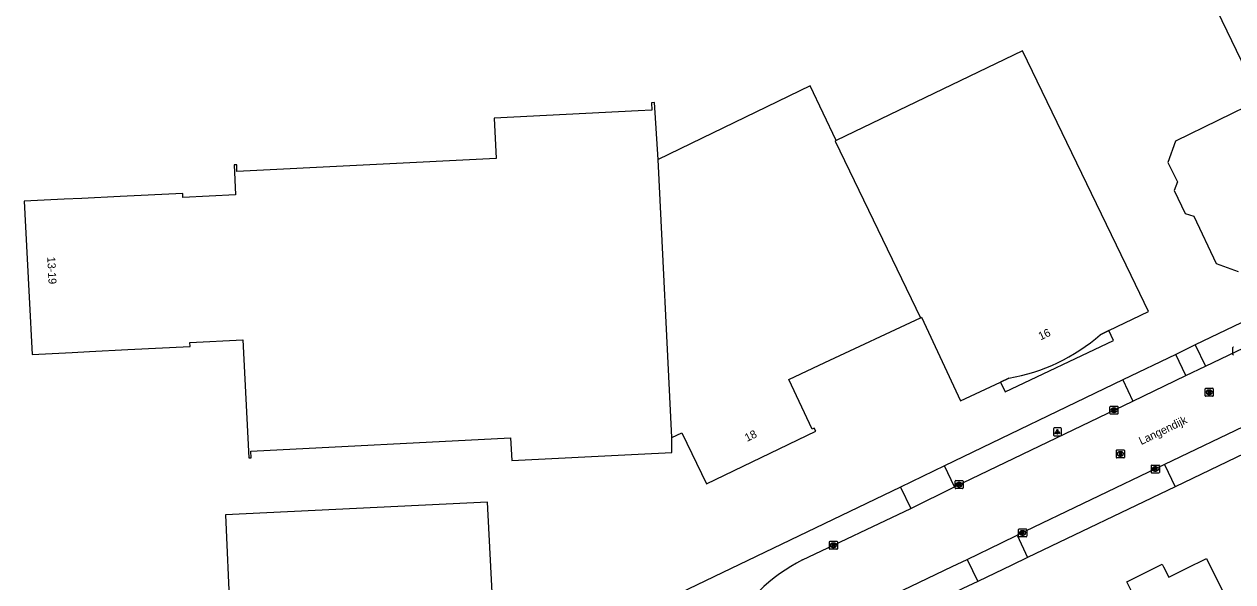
# Model space of a CAD drawing. Extents: x 157692 to 159670, y 381454 to 383289.
# Drawn here: x 157923.3 to 158074.3, y 381642.5 to 381712.2 of the extents above; entities that cross this region are included whole.
import ezdxf

# ---------------------------------------------------------------- set-up
doc = ezdxf.new("R2010")
doc.units = 0
for name, color, linetype in [('IMGEO_Kolk', 7, 'Continuous'), ('IMGEO_Lichtpunt', 7, 'Continuous'), ('IMGEO_Openbare_ruimte_label', 7, 'Continuous'), ('IMGEO_Pand', 7, 'Continuous'), ('IMGEO_Pand_nummerreeks', 7, 'Continuous'), ('IMGEO_Pand_overbouw', 7, 'Continuous'), ('IMGEO_Rijbaan_lokaal_gesloten', 7, 'Continuous'), ('IMGEO_Rioolput', 7, 'Continuous'), ('IMGEO_Voetpad_open', 7, 'Continuous')]:
    doc.layers.add(name, color=color, linetype=linetype)

msp = doc.modelspace()

# ---------------------------------------------------------------- linework, layer by layer
at = {"layer": 'IMGEO_Kolk'}
for p, q in [((158074.32, 381670.95), (158074.32, 381671.8)), ((158058.97, 381663.55), (158058.97, 381664.41)), ((158059.05, 381664.48), (158059.9, 381664.48)), ((158059.97, 381664.41), (158059.97, 381663.55)), ((158059.9, 381663.48), (158059.05, 381663.48)), ((158059.46, 381664.26), (158059.49, 381664.26)), ((158059.48, 381663.7), (158059.46, 381663.7)), ((158064.14, 381656.2), (158064.14, 381657.05)), ((158064.21, 381657.12), (158065.06, 381657.12)), ((158064.62, 381656.9), (158064.65, 381656.9)), ((158065.14, 381657.05), (158065.14, 381656.2)), ((158065.06, 381656.12), (158064.21, 381656.12)), ((158064.65, 381656.34), (158064.62, 381656.34)), ((158039.61, 381654.25), (158039.61, 381655.1)), ((158039.69, 381655.17), (158040.54, 381655.17)), ((158040.54, 381654.17), (158039.69, 381654.17)), ((158040.1, 381654.95), (158040.12, 381654.95)), ((158040.12, 381654.39), (158040.1, 381654.39)), ((158040.61, 381655.1), (158040.61, 381654.25)), ((158047.55, 381648.21), (158047.55, 381649.06)), ((158047.63, 381649.13), (158048.48, 381649.13)), ((158048.48, 381648.13), (158047.63, 381648.13)), ((158048.04, 381648.91), (158048.07, 381648.91)), ((158048.06, 381648.35), (158048.04, 381648.35)), ((158048.56, 381649.06), (158048.56, 381648.21)), ((158023.91, 381646.66), (158023.91, 381647.52)), ((158023.98, 381647.59), (158024.83, 381647.59)), ((158024.83, 381646.59), (158023.98, 381646.59)), ((158024.42, 381646.81), (158024.39, 381646.81)), ((158024.4, 381647.37), (158024.42, 381647.37)), ((158024.91, 381647.52), (158024.91, 381646.66))]:
    msp.add_line(p, q, dxfattribs=at)
for points in [[(158074.32, 381670.95), (158074.32, 381671.8)], [(158058.97, 381663.55), (158058.97, 381664.41)], [(158059.05, 381664.48), (158059.9, 381664.48)], [(158059.97, 381664.41), (158059.97, 381663.55)], [(158059.9, 381663.48), (158059.05, 381663.48)], [(158059.29, 381664.18), (158059.42, 381664.18), (158059.42, 381664.03), (158059.55, 381664.18), (158059.71, 381664.18), (158059.56, 381664.03), (158059.72, 381663.78), (158059.56, 381663.78), (158059.48, 381663.94), (158059.42, 381663.88), (158059.42, 381663.78), (158059.29, 381663.78), (158059.29, 381664.18)], [(158064.14, 381656.2), (158064.14, 381657.05)], [(158064.21, 381657.12), (158065.06, 381657.12)], [(158064.46, 381656.82), (158064.58, 381656.82), (158064.58, 381656.67), (158064.71, 381656.82), (158064.87, 381656.82), (158064.73, 381656.67), (158064.88, 381656.42), (158064.73, 381656.42), (158064.64, 381656.59), (158064.58, 381656.52), (158064.58, 381656.42), (158064.46, 381656.42), (158064.46, 381656.82)], [(158065.14, 381657.05), (158065.14, 381656.2)], [(158065.06, 381656.12), (158064.21, 381656.12)], [(158039.61, 381654.25), (158039.61, 381655.1)], [(158039.69, 381655.17), (158040.54, 381655.17)], [(158040.54, 381654.17), (158039.69, 381654.17)], [(158039.93, 381654.87), (158040.06, 381654.87), (158040.06, 381654.72), (158040.18, 381654.87), (158040.35, 381654.87), (158040.2, 381654.72), (158040.36, 381654.47), (158040.2, 381654.47), (158040.12, 381654.64), (158040.06, 381654.57), (158040.06, 381654.47), (158039.93, 381654.47), (158039.93, 381654.87)], [(158040.61, 381655.1), (158040.61, 381654.25)], [(158047.55, 381648.21), (158047.55, 381649.06)], [(158047.63, 381649.13), (158048.48, 381649.13)], [(158048.48, 381648.13), (158047.63, 381648.13)], [(158047.87, 381648.83), (158048, 381648.83), (158048, 381648.68), (158048.13, 381648.83), (158048.29, 381648.83), (158048.15, 381648.68), (158048.3, 381648.43), (158048.15, 381648.43), (158048.06, 381648.6), (158048, 381648.53), (158048, 381648.43), (158047.87, 381648.43), (158047.87, 381648.83)], [(158048.56, 381649.06), (158048.56, 381648.21)], [(158023.91, 381646.66), (158023.91, 381647.52)], [(158023.98, 381647.59), (158024.83, 381647.59)], [(158024.83, 381646.59), (158023.98, 381646.59)], [(158024.23, 381647.29), (158024.35, 381647.29), (158024.35, 381647.14), (158024.48, 381647.29), (158024.65, 381647.29), (158024.5, 381647.14), (158024.65, 381646.89), (158024.5, 381646.89), (158024.42, 381647.05), (158024.35, 381646.99), (158024.35, 381646.89), (158024.23, 381646.89), (158024.23, 381647.29)], [(158024.91, 381647.52), (158024.91, 381646.66)]]:
    msp.add_lwpolyline(points, dxfattribs=at)
for centre, start, end in [((158074.4, 381671.8), 91.552, 178.448), ((158074.4, 381671.8), 91.552, 178.448), ((158074.4, 381670.95), 181.552, 268.448), ((158074.4, 381670.95), 181.552, 268.448), ((158059.05, 381664.4), 91.552, 178.448), ((158059.05, 381664.4), 91.552, 178.448), ((158059.9, 381664.4), 1.552, 88.448), ((158059.9, 381664.4), 1.552, 88.448), ((158059.05, 381663.56), 181.552, 268.448), ((158059.05, 381663.56), 181.552, 268.448), ((158059.9, 381663.56), 271.552, 358.448), ((158059.9, 381663.56), 271.552, 358.448), ((158064.21, 381657.05), 91.552, 178.448), ((158064.21, 381657.05), 91.552, 178.448), ((158065.06, 381657.05), 1.552, 88.448), ((158065.06, 381657.05), 1.552, 88.448), ((158064.21, 381656.2), 181.552, 268.448), ((158064.21, 381656.2), 181.552, 268.448), ((158065.06, 381656.2), 271.552, 358.448), ((158065.06, 381656.2), 271.552, 358.448), ((158039.69, 381655.1), 91.552, 178.448), ((158039.69, 381655.1), 91.552, 178.448), ((158039.69, 381654.25), 181.552, 268.448), ((158039.69, 381654.25), 181.552, 268.448), ((158040.54, 381655.1), 1.552, 88.448), ((158040.54, 381655.1), 1.552, 88.448), ((158040.54, 381654.25), 271.552, 358.448), ((158040.54, 381654.25), 271.552, 358.448), ((158047.63, 381649.06), 91.552, 178.448), ((158047.63, 381649.06), 91.552, 178.448), ((158047.63, 381648.21), 181.552, 268.448), ((158047.63, 381648.21), 181.552, 268.448), ((158048.48, 381649.06), 1.552, 88.448), ((158048.48, 381649.06), 1.552, 88.448), ((158048.48, 381648.21), 271.552, 358.448), ((158048.48, 381648.21), 271.552, 358.448), ((158023.98, 381647.51), 91.552, 178.448), ((158023.98, 381647.51), 91.552, 178.448), ((158023.98, 381646.66), 181.552, 268.448), ((158023.98, 381646.66), 181.552, 268.448), ((158024.83, 381647.51), 1.552, 88.448), ((158024.83, 381647.51), 1.552, 88.448), ((158024.83, 381646.66), 271.552, 358.448), ((158024.83, 381646.66), 271.552, 358.448)]:
    msp.add_arc(centre, 0.0765, start, end, dxfattribs=at)
for centre, major_axis, ratio, start_param, end_param in [((158059.46, 381663.98), (-0.387, 0.002), 0.722429, 4.712389, 7.853982), ((158059.48, 381663.98), (-0.39, 0.002), 0.717154, 1.570796, 4.712389), ((158064.62, 381656.62), (-0.387, 0.002), 0.722429, 4.712389, 7.853982), ((158064.65, 381656.62), (-0.39, 0.002), 0.717154, 1.570796, 4.712389), ((158040.1, 381654.67), (-0.387, 0.002), 0.722429, 4.712389, 7.853982), ((158040.12, 381654.67), (-0.39, 0.002), 0.717154, 1.570796, 4.712389), ((158048.04, 381648.63), (-0.387, 0.002), 0.722429, 4.712389, 7.853982), ((158048.07, 381648.63), (-0.39, 0.002), 0.717154, 1.570796, 4.712389), ((158024.39, 381647.09), (-0.387, 0.002), 0.722429, 4.712389, 7.853982), ((158024.42, 381647.09), (-0.39, 0.002), 0.717154, 1.570796, 4.712389)]:
    msp.add_ellipse(centre, major_axis=major_axis, ratio=ratio, start_param=start_param, end_param=end_param, dxfattribs=at)
at = {"layer": 'IMGEO_Lichtpunt'}
for p, q in [((158051.9, 381661.66), (158051.9, 381660.86)), ((158051.9, 381661.66), (158051.9, 381660.86)), ((158052.81, 381661.76), (158052, 381661.76)), ((158052.81, 381661.76), (158052, 381661.76)), ((158052.9, 381660.86), (158052.9, 381661.66)), ((158052.9, 381660.86), (158052.9, 381661.66)), ((158052, 381660.76), (158052.81, 381660.76)), ((158052, 381660.76), (158052.81, 381660.76))]:
    msp.add_line(p, q, dxfattribs=at)
for points in [[(158052.28, 381661.33), (158052.32, 381661.3), (158052.13, 381661.04), (158052.09, 381661.06), (158052.28, 381661.33)], [(158052.49, 381661.3), (158052.53, 381661.33), (158052.71, 381661.06), (158052.68, 381661.04), (158052.49, 381661.3)], [(158052.38, 381661.28), (158052.43, 381661.28), (158052.43, 381660.96), (158052.38, 381660.96), (158052.38, 381661.28)]]:
    msp.add_lwpolyline(points, dxfattribs=at)
msp.add_circle((158052.4, 381661.46), 0.0994, dxfattribs=at)
for centre, start, end in [((158052, 381661.66), 90, 180), ((158052, 381661.66), 90, 180), ((158052.81, 381661.66), 0, 90), ((158052.81, 381661.66), 0, 90), ((158052, 381660.86), 180, 270), ((158052, 381660.86), 180, 270), ((158052.81, 381660.86), 270, 0), ((158052.81, 381660.86), 270, 360)]:
    msp.add_arc(centre, 0.0946, start, end, dxfattribs=at)
at = {"layer": 'IMGEO_Pand'}
for points in [[(158075.43, 381730.66), (158070.93, 381728.48), (158066.42, 381726.3), (158077.72, 381702.79), (158067.14, 381697.61), (158066.2, 381694.95), (158067.41, 381692.54), (158066.99, 381691.46), (158068.35, 381688.59), (158069.45, 381688.22), (158072.26, 381682.33), (158074.97, 381681.31)], [(158057.76, 381673.42), (158058.82, 381673.93), (158063.79, 381676.31), (158061.62, 381680.81), (158048.02, 381708.92), (158024.77, 381697.68)], [(158024.77, 381697.68), (158021.49, 381704.53), (158002.5, 381695.32)], [(158002.5, 381695.32), (158002.05, 381702.44), (158001.68, 381702.42), (158001.73, 381701.48), (158000, 381701.4), (157981.99, 381700.49), (157982.25, 381695.45), (157949.85, 381693.82), (157949.83, 381694.67), (157949.52, 381694.65), (157949.69, 381690.91), (157943.12, 381690.58), (157943.09, 381691.09), (157935.28, 381690.7), (157930.48, 381690.46), (157928.27, 381690.35), (157923.27, 381690.1), (157923.64, 381682.92), (157923.89, 381678.11), (157924.26, 381670.93), (157929.25, 381671.19), (157931.42, 381671.3), (157936.21, 381671.55), (157944, 381671.95), (157943.98, 381672.45), (157950.58, 381672.77), (157951.33, 381658), (157951.65, 381658.01), (157951.61, 381658.86), (157984.07, 381660.5), (157984.21, 381657.69), (158000, 381658.48), (158004.21, 381658.68), (158004.2, 381660.58)], [(158024.77, 381697.68), (158024.61, 381697.6), (158035.3, 381675.54)], [(158004.2, 381660.58), (158002.5, 381695.32)], [(158004.2, 381660.58), (158005.46, 381661.15), (158008.55, 381654.76), (158022.19, 381661.37), (158022.01, 381661.74), (158021.76, 381661.62), (158018.85, 381667.83), (158023.32, 381669.93), (158035.3, 381675.54)], [(158035.3, 381675.54), (158035.42, 381675.59), (158040.31, 381665.16), (158045.29, 381667.49), (158046.34, 381667.99)], [(157981.74, 381641.2), (157981.18, 381652.49), (157948.43, 381650.91), (157948.99, 381638.64)], [(158061.69, 381641.28), (158061.07, 381642.53), (158065.51, 381644.72), (158065.68, 381644.38), (158066.32, 381643.1), (158068.5, 381644.18), (158071.05, 381645.45), (158076.91, 381633.62), (158080.25, 381635.26), (158087.76, 381620.07), (158093.61, 381608.23), (158090.03, 381606.46), (158091.23, 381603.97), (158082.69, 381599.75), (158081.47, 381602.22), (158081.08, 381602.03), (158075.22, 381613.87), (158063.04, 381638.49)]]:
    msp.add_lwpolyline(points, dxfattribs=at)
msp.add_arc((158042.46, 381690.87), 23.21, 279.6368, 311.2392, dxfattribs=at)
at = {"layer": 'IMGEO_Pand_overbouw'}
for points in [[(158046.34, 381667.99), (158045.29, 381667.49), (158045.88, 381666.27), (158059.43, 381672.7), (158058.82, 381673.93)], [(158058.82, 381673.93), (158057.76, 381673.42)]]:
    msp.add_lwpolyline(points, dxfattribs=at)
msp.add_arc((158042.46, 381690.87), 23.21, 279.6368, 311.2392, dxfattribs=at)
at = {"layer": 'IMGEO_Rijbaan_lokaal_gesloten'}
for points in [[(158070.92, 381669.49), (158076.64, 381672.23)], [(158068.45, 381668.33), (158070.92, 381669.49)], [(158061.82, 381665.1), (158068.45, 381668.33)], [(158039.53, 381654.39), (158061.82, 381665.1)], [(158076.59, 381662.35), (158065.78, 381657.17)], [(158065.78, 381657.17), (158047.38, 381648.33)], [(158034.07, 381651.69), (158039.53, 381654.39)], [(158020.55, 381645.25), (158034.07, 381651.69)], [(158041.13, 381645.32), (158045.41, 381647.38), (158047.38, 381648.33)], [(158023.86, 381637.04), (158039.26, 381644.42), (158041.13, 381645.32)]]:
    msp.add_lwpolyline(points, dxfattribs=at)
msp.add_arc((158030, 381626.43), 21.06, 116.659, 153.2367, dxfattribs=at)
at = {"layer": 'IMGEO_Rioolput'}
for p, q in [((158070.87, 381665.79), (158070.87, 381666.64)), ((158070.95, 381666.72), (158071.8, 381666.72)), ((158071.36, 381666.5), (158071.39, 381666.5)), ((158071.38, 381665.94), (158071.36, 381665.94)), ((158071.87, 381666.64), (158071.87, 381665.79)), ((158071.8, 381665.72), (158070.95, 381665.72)), ((158059.77, 381658.08), (158059.77, 381658.94)), ((158059.84, 381659.01), (158060.69, 381659.01)), ((158060.25, 381658.79), (158060.28, 381658.79)), ((158060.77, 381658.94), (158060.77, 381658.08)), ((158060.69, 381658.01), (158059.84, 381658.01)), ((158060.28, 381658.23), (158060.25, 381658.23))]:
    msp.add_line(p, q, dxfattribs=at)
for points in [[(158070.87, 381665.79), (158070.87, 381666.64)], [(158070.95, 381666.72), (158071.8, 381666.72)], [(158071.46, 381666.41), (158071.21, 381666.42), (158071.21, 381666.02)], [(158071.21, 381666.02), (158071.33, 381666.02), (158071.33, 381666.18), (158071.34, 381666.18)], [(158071.39, 381666.34), (158071.33, 381666.34), (158071.33, 381666.25)], [(158071.33, 381666.25), (158071.38, 381666.25)], [(158071.39, 381666.15), (158071.46, 381666.02), (158071.6, 381666.02), (158071.54, 381666.14)], [(158071.87, 381666.64), (158071.87, 381665.79)], [(158071.8, 381665.72), (158070.95, 381665.72)], [(158059.77, 381658.08), (158059.77, 381658.94)], [(158059.84, 381659.01), (158060.69, 381659.01)], [(158060.36, 381658.71), (158060.1, 381658.71), (158060.1, 381658.31)], [(158060.1, 381658.31), (158060.23, 381658.31), (158060.23, 381658.47), (158060.24, 381658.47)], [(158060.28, 381658.63), (158060.23, 381658.63), (158060.23, 381658.55)], [(158060.23, 381658.55), (158060.28, 381658.55)], [(158060.28, 381658.44), (158060.36, 381658.31), (158060.5, 381658.31), (158060.43, 381658.44)], [(158060.77, 381658.94), (158060.77, 381658.08)], [(158060.69, 381658.01), (158059.84, 381658.01)]]:
    msp.add_lwpolyline(points, dxfattribs=at)
for centre, radius, start, end in [((158070.95, 381666.64), 0.0765, 91.552, 178.448), ((158070.95, 381666.64), 0.0765, 91.552, 178.448), ((158071.34, 381666.13), 0.0533, 26.0293, 88.6989), ((158071.37, 381666.44), 0.19, 274.7715, 282.9687), ((158071.39, 381666.24), 0.0964, 77.0061, 93.1865), ((158071.41, 381666.3), 0.0378, 276.6634, 79.6772), ((158071.46, 381666.3), 0.109, 350.3612, 89.416), ((158071.46, 381666.3), 0.112, 277.5842, 350.9817), ((158071.44, 381666.09), 0.108, 29.5134, 73.7905), ((158071.8, 381666.64), 0.0765, 1.552, 88.448), ((158071.8, 381666.64), 0.0765, 1.552, 88.448), ((158070.95, 381665.79), 0.0765, 181.552, 268.448), ((158070.95, 381665.79), 0.0765, 181.552, 268.448), ((158071.8, 381665.79), 0.0765, 271.552, 358.448), ((158071.8, 381665.79), 0.0765, 271.552, 358.448), ((158059.84, 381658.94), 0.0765, 91.552, 178.448), ((158059.84, 381658.94), 0.0765, 91.552, 178.448), ((158060.24, 381658.42), 0.0533, 26.0293, 88.6989), ((158060.29, 381658.53), 0.0964, 77.0061, 93.1865), ((158060.26, 381658.74), 0.19, 274.7715, 282.9687), ((158060.3, 381658.59), 0.0378, 276.6634, 79.6772), ((158060.35, 381658.6), 0.109, 350.3612, 89.416), ((158060.35, 381658.6), 0.112, 277.5842, 350.9817), ((158060.34, 381658.38), 0.108, 29.5134, 73.7905), ((158060.69, 381658.94), 0.0765, 1.552, 88.448), ((158060.69, 381658.94), 0.0765, 1.552, 88.448), ((158059.84, 381658.09), 0.0765, 181.552, 268.448), ((158059.84, 381658.09), 0.0765, 181.552, 268.448), ((158060.69, 381658.09), 0.0765, 271.552, 358.448), ((158060.69, 381658.09), 0.0765, 271.552, 358.448)]:
    msp.add_arc(centre, radius, start, end, dxfattribs=at)
for centre, major_axis, ratio, start_param, end_param in [((158071.36, 381666.22), (-0.387, 0.002), 0.722429, 4.712389, 7.853982), ((158071.38, 381666.22), (-0.39, 0.002), 0.717154, 1.570796, 4.712389), ((158060.25, 381658.51), (-0.387, 0.002), 0.722429, 4.712389, 7.853982), ((158060.28, 381658.51), (-0.39, 0.002), 0.717154, 1.570796, 4.712389)]:
    msp.add_ellipse(centre, major_axis=major_axis, ratio=ratio, start_param=start_param, end_param=end_param, dxfattribs=at)
at = {"layer": 'IMGEO_Voetpad_open'}
for points in [[(158075.38, 381674.88), (158069.61, 381672.13)], [(158069.61, 381672.13), (158067.21, 381670.95)], [(158069.61, 381672.13), (158070.92, 381669.49)], [(158067.21, 381670.95), (158060.57, 381667.76)], [(158068.45, 381668.33), (158067.21, 381670.95)], [(158060.57, 381667.76), (158038.28, 381657)], [(158060.57, 381667.76), (158061.82, 381665.1)], [(158077.96, 381659.61), (158067.11, 381654.39)], [(158038.28, 381657), (158032.78, 381654.36)], [(158039.53, 381654.39), (158038.28, 381657)], [(158065.78, 381657.17), (158067.11, 381654.39)], [(158032.78, 381654.36), (158005.22, 381641.11), (158005.47, 381636.38)], [(158032.78, 381654.36), (158034.07, 381651.69)], [(158067.11, 381654.39), (158048.67, 381645.55)], [(158047.38, 381648.33), (158048.67, 381645.55)], [(158041.13, 381645.32), (158042.44, 381642.56)], [(158048.67, 381645.55), (158046.69, 381644.6), (158042.44, 381642.56)], [(158042.44, 381642.56), (158040.6, 381641.67), (158025.19, 381634.25)]]:
    msp.add_lwpolyline(points, dxfattribs=at)

# ---------------------------------------------------------------- texts
at = {"layer": 'IMGEO_Openbare_ruimte_label'}
msp.add_text('Langendijk', height=1, rotation=25.6679, dxfattribs=at).set_placement((158062.88, 381659.61))
at = {"layer": 'IMGEO_Pand_nummerreeks'}
for s, rotation, p in [('13-19', 272.9516, (157926.15, 381683.13)), ('16', 25.3981, (158050.31, 381672.7)), ('18', 25.8516, (158013.61, 381660.01))]:
    msp.add_text(s, height=1, rotation=rotation, dxfattribs=at).set_placement(p)

doc.saveas('drawing.dxf')
